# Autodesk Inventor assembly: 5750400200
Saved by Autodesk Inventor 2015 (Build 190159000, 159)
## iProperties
Created: 2020-07
Part Number: 5750400200
Checked By: TraceParts S.A.
Catalog Web Link: www.traceparts.com
Document SubType Name: Assembly
Designer: TraceParts
Company: TraceParts S.A.
Author: TraceParts
REFERENCE: 5750400200
DESIGN: HXBR-355 ECOWATT (230V50/60HZ) V5 - 5750400200
SUPPLIER: Soler & Palau
TraceParts.PartNumber: 10-20122018-119605
TraceParts.PartTitle: HXBR-ECOWATT
TraceParts.InstanceId: 10-20122018-119605BUODET022K4X20WDA6F54ZLOR
TraceParts.PartStatus: Published
TraceParts.PartVersion: 1.0.2
TRACEPARTS: TRACEPARTS
TraceParts.PartLanguage: en
TraceParts.ClassPath: SOLER_PALAU:10-20122018-119605
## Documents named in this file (3)
- C:\TPO v2\SharedFS\Outgoing\5750400200.iam
- C:\TPO v2\SharedFS\Outgoing\5750400200_01.ipt
- C:\TPO v2\SharedFS\Outgoing\5750400200_02.ipt
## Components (2 placed, 2 different names)
1. 5750400200_01:1
2. 5750400200_02:1
